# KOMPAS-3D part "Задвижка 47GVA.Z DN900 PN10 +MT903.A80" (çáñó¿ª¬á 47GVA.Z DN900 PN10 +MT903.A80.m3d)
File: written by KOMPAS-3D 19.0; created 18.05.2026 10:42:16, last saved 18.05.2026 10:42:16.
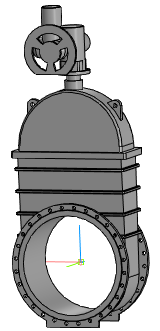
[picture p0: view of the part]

Document properties: Автор: Энергия; Полное имя файла: ..\Задвижка 47GVA.Z DN900 PN10 +MT903.A80.a3d

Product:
- Part/product: Задвижка 47GVA.Z DN900 PN10 +MT903.A80
    Масса: 3703.51
  - Body: Электропривод МТ903.А80 без блока управления
      Масса: 346.451
  - Body: Задвижка 47GVA.Z DN900 PN10 без исполнит. мех.
      Масса: 3357.06

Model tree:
1. Операция без истории:1
2. Операция без истории:2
